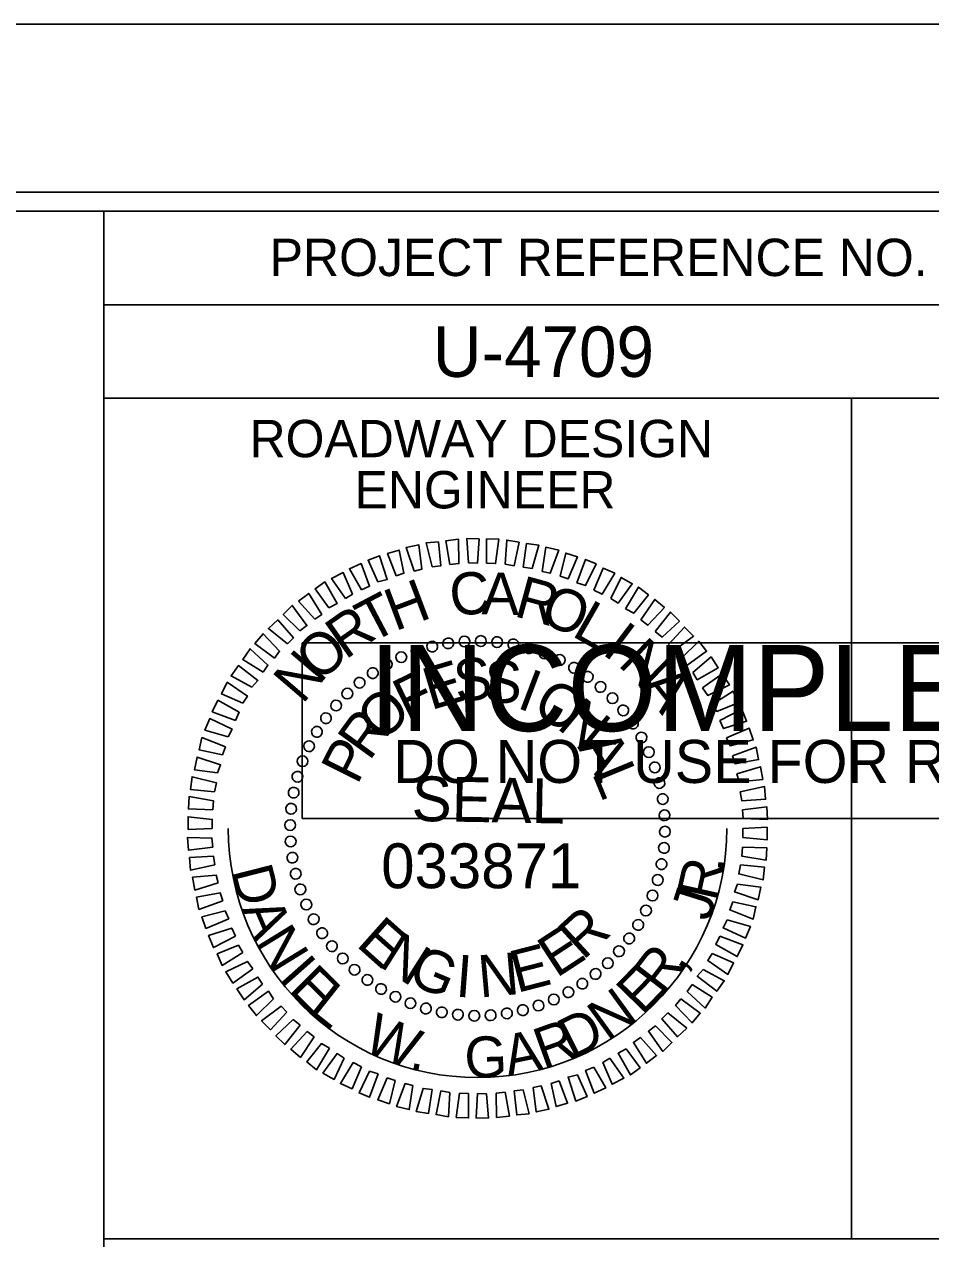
# Model space of a CAD drawing. Extents: x 958711 to 962106, y 831169 to 840840.
# Drawn here: x 960167.1 to 960288.4, y 839452.8 to 839615.4 of the extents above; entities that cross this region are included whole.
import ezdxf

# ---------------------------------------------------------------- set-up
doc = ezdxf.new("R2010")
doc.units = 0
for name, color, linetype in [('Scratch_Level_0', 7, 'Continuous'), ('Sheet Data Field CELL', 7, 'Continuous'), ('Sheet Plot Border Inside CELL', 7, 'Continuous'), ('Sheet Plot Border Outside CELL', 7, 'Continuous'), ('Sheet Professional Seal CELL', 7, 'Continuous'), ('Sheet Profile Grid Minor CELL', 7, 'Continuous'), ('Sheet Sticker Exception Certification CELL', 7, 'Continuous'), ('Sheet Sticker Incomplete CELL', 7, 'Continuous'), ('Sheet Typical CELL', 7, 'Continuous')]:
    doc.layers.add(name, color=color, linetype=linetype)

msp = doc.modelspace()

# ---------------------------------------------------------------- linework, layer by layer
at = {"layer": 'Scratch_Level_0'}
msp.add_arc((960227.77, 839507.76), 33.36, 180, 360, dxfattribs=at)
at = {"layer": 'Sheet Plot Border Inside CELL'}
msp.add_lwpolyline([(960390.3, 839592.94), (958723.8, 839592.94), (958723.8, 838537.84), (960390.3, 838537.84)], close=True, dxfattribs=at)
at = {"layer": 'Sheet Plot Border Outside CELL'}
msp.add_lwpolyline([(960394.8, 839615.39), (958710.8, 839615.39), (958710.8, 838515.39), (960394.8, 838515.39)], close=True, dxfattribs=at)
at = {"layer": 'Sheet Professional Seal CELL'}
for p, q in [((960219.57, 839531.51), (960219.57, 839531.51)), ((960221.67, 839532.11), (960221.67, 839532.11)), ((960223.87, 839532.51), (960223.87, 839532.51)), ((960226.02, 839532.81), (960226.02, 839532.81)), ((960228.22, 839532.86), (960228.22, 839532.86)), ((960230.42, 839532.71), (960230.42, 839532.71)), ((960232.57, 839532.36), (960232.57, 839532.36)), ((960234.67, 839531.91), (960234.67, 839531.91)), ((960217.57, 839530.71), (960217.57, 839530.71)), ((960236.77, 839531.21), (960236.77, 839531.21)), ((960238.77, 839530.31), (960238.77, 839530.31)), ((960213.72, 839528.56), (960213.72, 839528.56)), ((960215.62, 839529.71), (960215.62, 839529.71)), ((960240.72, 839529.31), (960240.72, 839529.31)), ((960211.97, 839527.31), (960211.97, 839527.31)), ((960242.52, 839528.06), (960242.52, 839528.06)), ((960244.27, 839526.71), (960244.27, 839526.71)), ((960210.32, 839525.81), (960210.32, 839525.81)), ((960245.82, 839525.21), (960245.82, 839525.21)), ((960208.82, 839524.26), (960208.82, 839524.26)), ((960247.32, 839523.56), (960247.32, 839523.56)), ((960207.47, 839522.51), (960207.47, 839522.51)), ((960248.57, 839521.81), (960248.57, 839521.81)), ((960206.22, 839520.71), (960206.22, 839520.71)), ((960205.22, 839518.76), (960205.22, 839518.76)), ((960249.72, 839519.91), (960249.72, 839519.91)), ((960250.72, 839517.96), (960250.72, 839517.96)), ((960204.32, 839516.76), (960204.32, 839516.76)), ((960251.52, 839515.96), (960251.52, 839515.96)), ((960203.62, 839514.66), (960203.62, 839514.66)), ((960252.12, 839513.86), (960252.12, 839513.86)), ((960203.17, 839512.56), (960203.17, 839512.56)), ((960202.82, 839510.41), (960202.82, 839510.41)), ((960252.52, 839511.66), (960252.52, 839511.66)), ((960252.82, 839509.51), (960252.82, 839509.51)), ((960202.67, 839508.21), (960202.67, 839508.21)), ((960227.77, 839507.76), (960227.77, 839507.76)), ((960252.87, 839507.31), (960252.87, 839507.31)), ((960202.72, 839506.01), (960202.72, 839506.01)), ((960252.72, 839505.11), (960252.72, 839505.11)), ((960203.02, 839503.86), (960203.02, 839503.86)), ((960252.37, 839502.96), (960252.37, 839502.96)), ((960203.42, 839501.66), (960203.42, 839501.66)), ((960251.92, 839500.86), (960251.92, 839500.86)), ((960204.02, 839499.56), (960204.02, 839499.56)), ((960204.82, 839497.56), (960204.82, 839497.56)), ((960251.22, 839498.76), (960251.22, 839498.76)), ((960250.32, 839496.76), (960250.32, 839496.76)), ((960205.82, 839495.61), (960205.82, 839495.61)), ((960249.32, 839494.81), (960249.32, 839494.81)), ((960206.97, 839493.71), (960206.97, 839493.71)), ((960248.07, 839493.01), (960248.07, 839493.01)), ((960208.22, 839491.96), (960208.22, 839491.96)), ((960246.72, 839491.26), (960246.72, 839491.26)), ((960209.72, 839490.31), (960209.72, 839490.31)), ((960245.22, 839489.71), (960245.22, 839489.71)), ((960211.27, 839488.81), (960211.27, 839488.81)), ((960243.57, 839488.21), (960243.57, 839488.21)), ((960213.02, 839487.46), (960213.02, 839487.46)), ((960214.82, 839486.21), (960214.82, 839486.21)), ((960241.82, 839486.96), (960241.82, 839486.96)), ((960216.77, 839485.21), (960216.77, 839485.21)), ((960237.97, 839484.81), (960237.97, 839484.81)), ((960239.92, 839485.81), (960239.92, 839485.81)), ((960218.77, 839484.31), (960218.77, 839484.31)), ((960220.87, 839483.61), (960220.87, 839483.61)), ((960222.97, 839483.16), (960222.97, 839483.16)), ((960225.12, 839482.81), (960225.12, 839482.81)), ((960231.67, 839483.01), (960231.67, 839483.01)), ((960233.87, 839483.41), (960233.87, 839483.41)), ((960235.97, 839484.01), (960235.97, 839484.01)), ((960227.32, 839482.66), (960227.32, 839482.66)), ((960229.52, 839482.71), (960229.52, 839482.71))]:
    msp.add_line(p, q, dxfattribs=at)
for points in [[(960224.07, 839543.06), (960223.52, 839546.26), (960225.22, 839546.46), (960225.27, 839543.21)], [(960226.57, 839543.31), (960226.32, 839546.56), (960227.97, 839546.51), (960227.77, 839543.26)], [(960228.97, 839543.26), (960228.97, 839546.51), (960230.62, 839546.46), (960230.17, 839543.21)], [(960231.47, 839543.11), (960231.67, 839546.36), (960233.32, 839546.06), (960232.67, 839542.91)], [(960216.87, 839541.56), (960215.72, 839544.56), (960217.27, 839545.01), (960217.92, 839541.91)], [(960219.27, 839542.21), (960218.22, 839545.36), (960219.92, 839545.71), (960220.32, 839542.46)], [(960221.67, 839542.76), (960220.87, 839545.96), (960222.52, 839546.11), (960222.87, 839542.91)], [(960233.87, 839542.71), (960234.32, 839545.91), (960235.97, 839545.66), (960235.07, 839542.56)], [(960236.42, 839542.16), (960236.92, 839545.41), (960238.62, 839545.01), (960237.47, 839541.91)], [(960238.82, 839541.51), (960239.57, 839544.61), (960241.12, 839544.11), (960239.87, 839541.16)], [(960212.22, 839539.71), (960210.62, 839542.51), (960212.17, 839543.21), (960213.32, 839540.16)], [(960214.42, 839540.76), (960213.12, 839543.66), (960214.62, 839544.26), (960215.67, 839541.06)], [(960241.07, 839540.61), (960242.22, 839543.76), (960243.62, 839543.16), (960242.22, 839540.26)], [(960210.07, 839538.51), (960208.22, 839541.21), (960209.77, 839542.01), (960211.02, 839539.11)], [(960243.32, 839539.66), (960244.57, 839542.61), (960246.12, 839541.91), (960244.42, 839539.11)], [(960245.62, 839538.51), (960246.97, 839541.36), (960248.47, 839540.51), (960246.57, 839537.91)], [(960207.87, 839537.26), (960206.02, 839539.81), (960207.32, 839540.76), (960208.97, 839537.86)], [(960247.57, 839537.16), (960249.32, 839540.06), (960250.62, 839539.01), (960248.67, 839536.56)], [(960205.97, 839535.76), (960203.82, 839538.16), (960205.17, 839539.21), (960206.92, 839536.41)], [(960249.62, 839535.66), (960251.47, 839538.41), (960252.77, 839537.31), (960250.57, 839534.96)], [(960203.97, 839534.21), (960201.77, 839536.41), (960202.97, 839537.61), (960204.92, 839534.91)], [(960251.52, 839534.11), (960253.57, 839536.71), (960254.77, 839535.51), (960252.47, 839533.36)], [(960202.32, 839532.46), (960199.77, 839534.51), (960201.02, 839535.66), (960203.12, 839533.26)], [(960200.57, 839530.56), (960197.97, 839532.51), (960199.07, 839533.81), (960201.27, 839531.46)], [(960253.32, 839532.36), (960255.47, 839534.71), (960256.67, 839533.51), (960254.07, 839531.56)], [(960199.07, 839528.66), (960196.37, 839530.36), (960197.32, 839531.81), (960199.72, 839529.61)], [(960255.07, 839530.56), (960257.37, 839532.81), (960258.42, 839531.46), (960255.77, 839529.56)], [(960256.57, 839528.61), (960259.02, 839530.71), (960259.97, 839529.26), (960257.17, 839527.66)], [(960197.57, 839526.66), (960194.77, 839528.16), (960195.77, 839529.56), (960198.37, 839527.56)], [(960257.87, 839526.56), (960260.52, 839528.46), (960261.47, 839526.96), (960258.57, 839525.56)], [(960196.37, 839524.51), (960193.52, 839525.76), (960194.27, 839527.31), (960196.97, 839525.46)], [(960259.17, 839524.36), (960261.97, 839526.11), (960262.62, 839524.56), (960259.77, 839523.41)], [(960195.37, 839522.21), (960192.27, 839523.36), (960193.02, 839524.91), (960195.87, 839523.31)], [(960260.17, 839522.21), (960263.12, 839523.71), (960263.77, 839522.11), (960260.67, 839521.11)], [(960194.37, 839520.01), (960191.27, 839520.91), (960191.92, 839522.46), (960194.92, 839521.06)], [(960261.07, 839519.86), (960264.12, 839521.16), (960264.67, 839519.61), (960261.57, 839518.81)], [(960193.62, 839517.61), (960190.52, 839518.26), (960190.87, 839519.91), (960194.02, 839518.66)], [(960261.87, 839517.46), (960265.07, 839518.61), (960265.37, 839516.96), (960262.22, 839516.41)], [(960192.97, 839515.21), (960189.87, 839515.61), (960190.22, 839517.31), (960193.37, 839516.26)], [(960262.47, 839515.06), (960265.62, 839516.01), (960265.92, 839514.31), (960262.77, 839514.01)], [(960192.57, 839512.66), (960189.37, 839512.96), (960189.57, 839514.66), (960192.82, 839513.86)], [(960192.32, 839510.26), (960189.07, 839510.36), (960189.17, 839512.01), (960192.42, 839511.46)], [(960262.92, 839512.66), (960266.17, 839513.36), (960266.32, 839511.66), (960263.12, 839511.46)], [(960263.22, 839510.26), (960266.47, 839510.66), (960266.57, 839508.96), (960263.32, 839509.06)], [(960192.27, 839507.76), (960189.02, 839507.61), (960189.02, 839509.31), (960192.27, 839508.96)], [(960263.27, 839507.76), (960266.52, 839507.91), (960266.52, 839506.21), (960263.27, 839506.56)], [(960192.32, 839505.26), (960189.07, 839504.86), (960188.97, 839506.56), (960192.22, 839506.46)], [(960192.62, 839502.86), (960189.37, 839502.16), (960189.22, 839503.86), (960192.42, 839504.06)], [(960263.22, 839505.26), (960266.47, 839505.16), (960266.37, 839503.51), (960263.12, 839504.06)], [(960262.97, 839502.86), (960266.17, 839502.56), (960265.97, 839500.86), (960262.72, 839501.66)], [(960193.07, 839500.46), (960189.92, 839499.51), (960189.62, 839501.21), (960192.77, 839501.51)], [(960193.67, 839498.06), (960190.47, 839496.91), (960190.17, 839498.56), (960193.32, 839499.11)], [(960262.57, 839500.31), (960265.67, 839499.91), (960265.32, 839498.21), (960262.17, 839499.26)], [(960261.92, 839497.91), (960265.02, 839497.26), (960264.67, 839495.61), (960261.52, 839496.86)], [(960194.47, 839495.66), (960191.42, 839494.36), (960190.87, 839495.91), (960193.97, 839496.71)], [(960195.37, 839493.31), (960192.42, 839491.81), (960191.77, 839493.41), (960194.87, 839494.41)], [(960261.17, 839495.51), (960264.27, 839494.61), (960263.62, 839493.06), (960260.62, 839494.46)], [(960260.17, 839493.31), (960263.27, 839492.16), (960262.52, 839490.61), (960259.67, 839492.21)], [(960196.37, 839491.16), (960193.57, 839489.41), (960192.92, 839490.96), (960195.77, 839492.11)], [(960259.17, 839491.01), (960262.02, 839489.76), (960261.27, 839488.21), (960258.57, 839490.06)], [(960197.67, 839488.96), (960195.02, 839487.06), (960194.07, 839488.56), (960196.97, 839489.96)], [(960198.97, 839486.91), (960196.52, 839484.81), (960195.57, 839486.26), (960198.37, 839487.86)], [(960257.97, 839488.86), (960260.77, 839487.36), (960259.77, 839485.96), (960257.17, 839487.96)], [(960256.47, 839486.86), (960259.17, 839485.16), (960258.22, 839483.71), (960255.82, 839485.91)], [(960200.47, 839484.96), (960198.17, 839482.71), (960197.12, 839484.06), (960199.77, 839485.96)], [(960254.97, 839484.96), (960257.57, 839483.01), (960256.47, 839481.71), (960254.27, 839484.06)], [(960202.22, 839483.16), (960200.07, 839480.81), (960198.87, 839482.01), (960201.47, 839483.96)], [(960253.22, 839483.06), (960255.77, 839481.01), (960254.52, 839479.86), (960252.42, 839482.26)], [(960204.02, 839481.41), (960201.97, 839478.81), (960200.77, 839480.01), (960203.07, 839482.16)], [(960251.57, 839481.31), (960253.77, 839479.11), (960252.57, 839477.91), (960250.62, 839480.61)], [(960205.92, 839479.86), (960204.07, 839477.11), (960202.77, 839478.21), (960204.97, 839480.56)], [(960249.57, 839479.76), (960251.72, 839477.36), (960250.37, 839476.31), (960248.62, 839479.11)], [(960207.97, 839478.36), (960206.22, 839475.46), (960204.92, 839476.51), (960206.87, 839478.96)], [(960247.67, 839478.26), (960249.52, 839475.71), (960248.22, 839474.76), (960246.57, 839477.66)], [(960209.92, 839477.01), (960208.57, 839474.16), (960207.07, 839475.01), (960208.97, 839477.61)], [(960212.22, 839475.86), (960210.97, 839472.91), (960209.42, 839473.61), (960211.12, 839476.41)], [(960245.47, 839477.01), (960247.32, 839474.31), (960245.77, 839473.51), (960244.52, 839476.41)], [(960214.47, 839474.91), (960213.32, 839471.76), (960211.92, 839472.36), (960213.32, 839475.26)], [(960241.12, 839474.76), (960242.42, 839471.86), (960240.92, 839471.26), (960239.87, 839474.46)], [(960243.32, 839475.81), (960244.92, 839473.01), (960243.37, 839472.31), (960242.22, 839475.36)], [(960216.72, 839474.01), (960215.97, 839470.91), (960214.42, 839471.41), (960215.67, 839474.36)], [(960219.12, 839473.36), (960218.62, 839470.11), (960216.92, 839470.51), (960218.07, 839473.61)], [(960236.27, 839473.31), (960237.32, 839470.16), (960235.62, 839469.81), (960235.22, 839473.06)], [(960238.67, 839473.96), (960239.82, 839470.96), (960238.27, 839470.51), (960237.62, 839473.61)], [(960221.67, 839472.81), (960221.22, 839469.61), (960219.57, 839469.86), (960220.47, 839472.96)], [(960224.07, 839472.41), (960223.87, 839469.16), (960222.22, 839469.46), (960222.87, 839472.61)], [(960226.57, 839472.26), (960226.57, 839469.01), (960224.92, 839469.06), (960225.37, 839472.31)], [(960228.97, 839472.21), (960229.22, 839468.96), (960227.57, 839469.01), (960227.77, 839472.26)], [(960231.47, 839472.46), (960232.02, 839469.26), (960230.32, 839469.06), (960230.27, 839472.31)], [(960233.87, 839472.76), (960234.67, 839469.56), (960233.02, 839469.41), (960232.67, 839472.61)]]:
    msp.add_lwpolyline(points, close=True, dxfattribs=at)
for centre, major_axis in [((960223.84, 839532.53), (-0.113, 0.711)), ((960226.02, 839532.78), (-0.05, 0.718)), ((960228.2, 839532.84), (0.013, 0.72)), ((960230.39, 839532.7), (0.075, 0.716)), ((960232.55, 839532.38), (0.137, 0.707)), ((960219.6, 839531.47), (-0.234, 0.681)), ((960221.7, 839532.09), (-0.174, 0.699)), ((960234.68, 839531.87), (0.198, 0.692)), ((960236.75, 839531.17), (0.258, 0.672)), ((960215.61, 839529.69), (-0.349, 0.63)), ((960217.56, 839530.67), (-0.293, 0.658)), ((960238.76, 839530.3), (0.316, 0.647)), ((960240.68, 839529.26), (0.371, 0.617)), ((960213.74, 839528.55), (-0.403, 0.597)), ((960242.51, 839528.05), (0.423, 0.582)), ((960211.98, 839527.25), (-0.453, 0.56)), ((960244.22, 839526.69), (0.472, 0.543)), ((960208.84, 839524.21), (-0.543, 0.472)), ((960210.34, 839525.8), (-0.5, 0.518)), ((960245.81, 839525.18), (0.518, 0.5)), ((960247.26, 839523.54), (0.56, 0.453)), ((960207.48, 839522.5), (-0.582, 0.423)), ((960248.56, 839521.78), (0.597, 0.403)), ((960206.27, 839520.68), (-0.617, 0.371)), ((960249.7, 839519.92), (0.63, 0.349)), ((960205.22, 839518.75), (-0.647, 0.316)), ((960250.68, 839517.96), (0.658, 0.293)), ((960204.35, 839516.75), (-0.672, 0.258)), ((960203.66, 839514.67), (-0.692, 0.198)), ((960251.48, 839515.92), (0.681, 0.234)), ((960252.1, 839513.83), (0.699, 0.174)), ((960203.15, 839512.54), (-0.707, 0.137)), ((960252.54, 839511.68), (0.711, 0.113)), ((960202.82, 839510.38), (-0.716, 0.075)), ((960202.69, 839508.2), (-0.72, 0.013)), ((960252.78, 839509.51), (0.718, 0.05)), ((960252.84, 839507.32), (0.72, -0.013)), ((960202.75, 839506.01), (-0.718, -0.05)), ((960252.71, 839505.14), (0.716, -0.075)), ((960202.99, 839503.84), (-0.711, -0.113)), ((960203.43, 839501.69), (-0.699, -0.174)), ((960252.38, 839502.97), (0.707, -0.137)), ((960251.87, 839500.85), (0.692, -0.198)), ((960204.05, 839499.59), (-0.681, -0.234)), ((960251.18, 839498.77), (0.672, -0.258)), ((960204.85, 839497.56), (-0.658, -0.293)), ((960250.31, 839496.76), (0.647, -0.316)), ((960205.83, 839495.6), (-0.63, -0.349)), ((960206.97, 839493.73), (-0.597, -0.403)), ((960249.26, 839494.84), (0.617, -0.371)), ((960208.27, 839491.98), (-0.56, -0.453)), ((960248.06, 839493.02), (0.582, -0.423)), ((960209.72, 839490.34), (-0.518, -0.5)), ((960246.69, 839491.31), (0.543, -0.472)), ((960211.31, 839488.83), (-0.472, -0.543)), ((960245.19, 839489.72), (0.5, -0.518)), ((960213.02, 839487.47), (-0.423, -0.582)), ((960241.79, 839486.97), (0.403, -0.597)), ((960243.55, 839488.27), (0.453, -0.56)), ((960214.85, 839486.26), (-0.371, -0.617)), ((960216.77, 839485.22), (-0.316, -0.647)), ((960239.92, 839485.82), (0.349, -0.63)), ((960218.78, 839484.35), (-0.258, -0.672)), ((960220.85, 839483.65), (-0.198, -0.692)), ((960235.93, 839484.05), (0.234, -0.681)), ((960237.97, 839484.85), (0.293, -0.658)), ((960222.98, 839483.14), (-0.137, -0.707)), ((960225.14, 839482.82), (-0.075, -0.716)), ((960227.33, 839482.68), (-0.013, -0.72)), ((960229.51, 839482.74), (0.05, -0.718)), ((960231.69, 839482.99), (0.113, -0.711)), ((960233.83, 839483.42), (0.174, -0.699))]:
    msp.add_ellipse(centre, major_axis=major_axis, ratio=0.999708, dxfattribs=at)
at = {"layer": 'Sheet Sticker Exception Certification CELL'}
for p, q in [((960177.75, 839429.34), (960177.75, 839452.84)), ((960177.75, 839452.84), (960377.79, 839452.84))]:
    msp.add_line(p, q, dxfattribs=at)
at = {"layer": 'Sheet Sticker Incomplete CELL'}
msp.add_lwpolyline([(960204.3, 839509.09), (960204.3, 839532.59), (960351.3, 839532.59), (960351.3, 839509.09)], close=True, dxfattribs=at)
at = {"layer": 'Sheet Typical CELL'}
for p, q in [((960177.75, 839577.84), (960377.8, 839577.84)), ((960277.8, 839565.34), (960277.8, 839452.89))]:
    msp.add_line(p, q, dxfattribs=at)
for points in [[(960377.8, 839590.39), (958877.8, 839590.39), (958877.8, 838540.39), (960377.8, 838540.39)], [(960177.75, 839590.39), (960377.8, 839590.39), (960377.8, 839565.34), (960177.75, 839565.34)], [(960177.75, 839565.34), (960277.8, 839565.34), (960277.8, 839452.84), (960177.75, 839452.84)], [(960277.8, 839565.34), (960377.8, 839565.34), (960377.8, 839452.84), (960277.8, 839452.84)]]:
    msp.add_lwpolyline(points, close=True, dxfattribs=at)

# ---------------------------------------------------------------- texts
at = {"layer": 'Sheet Data Field CELL'}
msp.add_text('U-4709', height=6.75, dxfattribs=at).set_placement((960221.78, 839568.19))
at = {"layer": 'Sheet Professional Seal CELL'}
for s, height, rotation, p in [('C', 5.64, 6.2199, (960224.32, 839536.11)), ('A', 5.64, 359.0203, (960228.27, 839536.41)), ('R', 5.64, 344.6211, (960232.47, 839536.21)), ('H', 5.64, 20.6195, (960216.72, 839534.11)), ('O', 5.64, 337.4212, (960235.82, 839535.46)), ('T', 5.64, 27.8198, (960213.47, 839532.46)), ('L', 5.64, 330.2209, (960240.22, 839533.61)), ('R', 5.64, 35.0205, (960210.07, 839530.26)), ('I', 5.64, 323.0201, (960244.27, 839531.21)), ('O', 5.64, 42.2217, (960206.62, 839527.16)), ('N', 5.64, 315.8189, (960246.42, 839529.66)), ('N', 5.64, 49.4235, (960204.32, 839524.26)), ('E', 5.64, 16.6111, (960221.52, 839523.56)), ('S', 5.64, 7.2556, (960224.97, 839524.61)), ('S', 5.64, 357.9004, (960228.57, 839524.66)), ('F', 5.64, 25.967, (960218.32, 839522.06)), ('I', 5.64, 339.1896, (960232.87, 839523.96)), ('A', 5.64, 308.6172, (960249.37, 839526.71)), ('O', 5.64, 329.8335, (960234.87, 839523.26)), ('O', 5.64, 44.6812, (960215.02, 839519.11)), ('N', 5.64, 320.4766, (960238.22, 839521.26)), ('R', 5.64, 54.0397, (960213.27, 839516.66)), ('P', 5.64, 63.3989, (960211.67, 839513.46)), ('A', 5.64, 301.7603, (960241.07, 839518.66)), ('L', 5.64, 292.4008, (960243.02, 839515.21)), ('SEAL', 5.998, 359, (960218.92, 839508.76)), ('E', 5.64, 318.2769, (960211.37, 839492.11)), ('R', 5.64, 42.4814, (960241.87, 839490.01)), ('E', 5.64, 33.1241, (960238.32, 839487.66)), ('N', 5.64, 327.634, (960214.37, 839489.41)), ('G', 5.64, 336.9902, (960218.17, 839487.16)), ('N', 5.64, 5.0564, (960228.07, 839485.11)), ('E', 5.64, 14.4118, (960233.02, 839485.71)), ('I', 5.64, 355.7012, (960224.72, 839485.26))]:
    msp.add_text(s, height=height, rotation=rotation, dxfattribs=at).set_placement(p)
at = {"layer": 'Sheet Profile Grid Minor CELL'}
msp.add_text('033871', height=5.998, dxfattribs=at).set_placement((960214.87, 839499.75))
for s, rotation, p in [('D', 284.2682, (960194.77, 839502.12)), ('R', 77.3541, (960259.74, 839497.86)), ('.', 84.2805, (960260.7, 839501.79)), ('J', 72.4855, (960258.78, 839495.18)), ('A', 293.4128, (960196.09, 839496.95)), ('N', 301.5986, (960197.95, 839492.55)), ('R', 52.3788, (960252.57, 839485.28)), ('I', 311.5304, (960201.02, 839487.63)), ('E', 315.0508, (960202.31, 839486.03)), ('E', 45.7958, (960249.83, 839482.59)), (',', 59.3052, (960255.1, 839488.44)), ('L', 321.6338, (960204.97, 839483.25)), ('N', 35.8641, (960245.15, 839479.16)), ('W', 336.8891, (960212.22, 839478.12)), ('D', 26.7195, (960240.39, 839476.76)), ('R', 19.793, (960236.56, 839475.46)), ('G', 1.6755, (960226.08, 839474.33)), ('A', 11.6072, (960231.87, 839474.54)), ('.', 348.4952, (960218.5, 839475.6))]:
    msp.add_text(s, height=5.5, rotation=rotation, dxfattribs=at).set_placement(p)
at = {"layer": 'Sheet Sticker Incomplete CELL'}
for s, height, p in [('INCOMPLETE PLANS', 11.52, (960213.25, 839520.79)), ('DO NOT USE FOR R/W ACQUISITION', 5.76, (960216.5, 839513.84))]:
    msp.add_text(s, height=height, dxfattribs=at).set_placement(p)
at = {"layer": 'Sheet Typical CELL'}
for s, height, p in [('PROJECT REFERENCE NO.', 5.0001, (960199.95, 839581.69)), ('ROADWAY DESIGN', 5.0001, (960197.25, 839557.44)), ('ENGINEER', 5, (960211.3, 839550.59))]:
    msp.add_text(s, height=height, dxfattribs=at).set_placement(p)

doc.saveas('drawing.dxf')
